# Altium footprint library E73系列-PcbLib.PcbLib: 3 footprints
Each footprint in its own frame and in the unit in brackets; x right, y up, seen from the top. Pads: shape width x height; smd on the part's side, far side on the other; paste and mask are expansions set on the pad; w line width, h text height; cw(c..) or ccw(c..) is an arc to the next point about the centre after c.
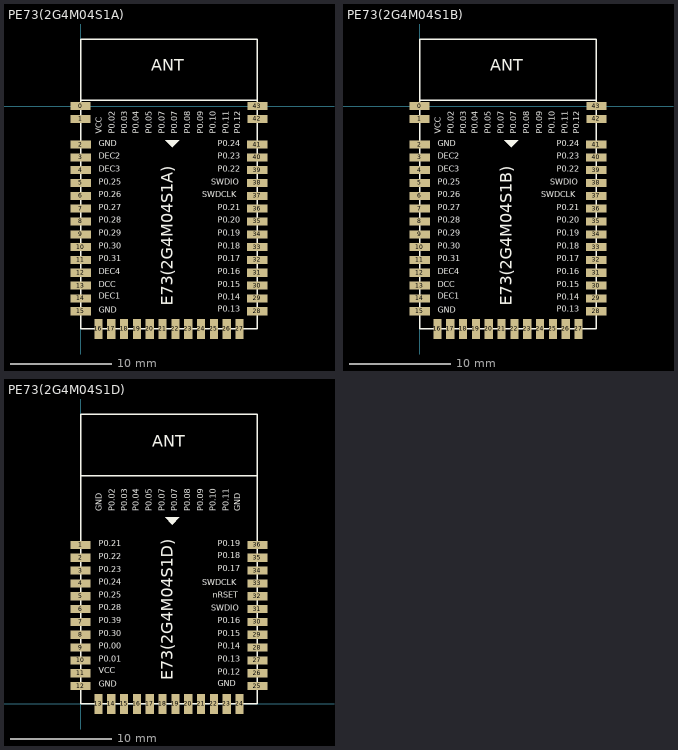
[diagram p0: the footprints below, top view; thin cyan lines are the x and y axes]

## PE73(2G4M04S1A) [mm] "28.7mm*17.5mm*2.60mm-S"
pads (44):
  rect 2x0.8 smd: 0(0,0) 1(0,-1.27) 2(0.02,-3.81) 3(0.02,-5.08) 4(0.02,-6.35) 5(0.02,-7.62) 6(0.02,-8.89) 7(0.02,-10.16) 8(0.02,-11.43) 9(0.02,-12.7) 10(0.02,-13.97) 11(0.02,-15.24) 12(0.02,-16.51) 13(0.02,-17.78) 14(0.02,-19.05) 15(0.02,-20.32) 28(17.48,-20.32) 29(17.48,-19.05) 30(17.48,-17.78) 31(17.48,-16.51) 32(17.48,-15.24) 33(17.48,-13.97) 34(17.48,-12.7) 35(17.48,-11.43) 36(17.48,-10.16) 37(17.48,-8.89) 38(17.48,-7.62) 39(17.48,-6.35) 40(17.48,-5.08) 41(17.48,-3.81) 42(17.5,-1.27) 43(17.5,0)
  rect 0.8x2 smd: 16(1.765,-22.065) 17(3.035,-22.065) 18(4.305,-22.065) 19(5.575,-22.065) 20(6.845,-22.065) 21(8.115,-22.065) 22(9.385,-22.065) 23(10.655,-22.065) 24(11.925,-22.065) 25(13.195,-22.065) 26(14.465,-22.065) 27(15.735,-22.065)
Top Overlay:
  region: 8.37,-3.375 9.76,-3.385 9.08,-4.085 8.36,-3.385
  lines w0.127: 0,0.573 17.467,0.573 ; 0,-22.065 17.5,-22.065 17.5,6.635 0,6.635 0,-22.065
  text "E73(2G4M04S1A)" at 9.525,-19.779 h2
  text "ANT" at 6.985,3.081 h2
  text "GND" at 1.778,-4.158 h1
  text "DEC2" at 1.778,-5.428 h1
  text "DEC3" at 1.778,-6.698 h1
  text "P0.25" at 1.778,-7.968 h1
  text "P0.26" at 1.778,-9.238 h1
  text "P0.27" at 1.778,-10.508 h1
  text "P0.28" at 1.778,-11.778 h1
  text "P0.29" at 1.778,-13.048 h1
  text "P0.30" at 1.778,-14.318 h1
  text "P0.31" at 1.778,-15.588 h1
  text "DEC4" at 1.778,-16.858 h1
  text "DCC" at 1.778,-18.128 h1
  text "DEC1" at 1.778,-19.271 h1
  text "GND" at 1.778,-20.668 h1
  text "P0.13" at 13.589,-20.541 h1
  text "P0.14" at 13.589,-19.398 h1
  text "P0.15" at 13.589,-18.128 h1
  text "P0.16" at 13.589,-16.858 h1
  text "P0.17" at 13.589,-15.588 h1
  text "P0.18" at 13.589,-14.318 h1
  text "P0.19" at 13.589,-13.048 h1
  text "P0.20" at 13.589,-11.778 h1
  text "P0.21" at 13.589,-10.508 h1
  text "SWDCLK" at 12.065,-9.238 h1
  text "SWDIO" at 12.954,-7.968 h1
  text "P0.22" at 13.589,-6.698 h1
  text "P0.23" at 13.589,-5.428 h1
  text "P0.24" at 13.589,-4.158 h1
  text "VCC" at 2.286,-2.761 h1
  text "P0.02" at 3.556,-2.761 h1
  text "P0.03" at 4.826,-2.761 h1
  text "P0.04" at 5.969,-2.761 h1
  text "P0.05" at 7.239,-2.761 h1
  text "P0.07" at 8.509,-2.761 h1
  text "P0.07" at 9.779,-2.761 h1
  text "P0.08" at 11.049,-2.761 h1
  text "P0.09" at 12.319,-2.761 h1
  text "P0.10" at 13.589,-2.761 h1
  text "P0.11" at 14.859,-2.761 h1
  text "P0.12" at 16.009,-2.77 h1

## PE73(2G4M04S1B) [mm] "28.7mm*17.5mm*2.60mm-S"
pads (44):
  rect 2x0.8 smd: 0(0,0) 1(0,-1.27) 2(0.02,-3.81) 3(0.02,-5.08) 4(0.02,-6.35) 5(0.02,-7.62) 6(0.02,-8.89) 7(0.02,-10.16) 8(0.02,-11.43) 9(0.02,-12.7) 10(0.02,-13.97) 11(0.02,-15.24) 12(0.02,-16.51) 13(0.02,-17.78) 14(0.02,-19.05) 15(0.02,-20.32) 28(17.48,-20.32) 29(17.48,-19.05) 30(17.48,-17.78) 31(17.48,-16.51) 32(17.48,-15.24) 33(17.48,-13.97) 34(17.48,-12.7) 35(17.48,-11.43) 36(17.48,-10.16) 37(17.48,-8.89) 38(17.48,-7.62) 39(17.48,-6.35) 40(17.48,-5.08) 41(17.48,-3.81) 42(17.5,-1.27) 43(17.5,0)
  rect 0.8x2 smd: 16(1.765,-22.065) 17(3.035,-22.065) 18(4.305,-22.065) 19(5.575,-22.065) 20(6.845,-22.065) 21(8.115,-22.065) 22(9.385,-22.065) 23(10.655,-22.065) 24(11.925,-22.065) 25(13.195,-22.065) 26(14.465,-22.065) 27(15.735,-22.065)
Top Overlay:
  region: 8.37,-3.375 9.76,-3.385 9.08,-4.085 8.36,-3.385
  lines w0.127: 0,0.573 17.467,0.573 ; 0,-22.065 17.5,-22.065 17.5,6.635 0,6.635 0,-22.065
  text "E73(2G4M04S1B)" at 9.525,-19.779 h2
  text "ANT" at 6.985,3.081 h2
  text "GND" at 1.778,-4.158 h1
  text "DEC2" at 1.778,-5.428 h1
  text "DEC3" at 1.778,-6.698 h1
  text "P0.25" at 1.778,-7.968 h1
  text "P0.26" at 1.778,-9.238 h1
  text "P0.27" at 1.778,-10.508 h1
  text "P0.28" at 1.778,-11.778 h1
  text "P0.29" at 1.778,-13.048 h1
  text "P0.30" at 1.778,-14.318 h1
  text "P0.31" at 1.778,-15.588 h1
  text "DEC4" at 1.778,-16.858 h1
  text "DCC" at 1.778,-18.128 h1
  text "DEC1" at 1.778,-19.271 h1
  text "GND" at 1.778,-20.668 h1
  text "P0.13" at 13.589,-20.541 h1
  text "P0.14" at 13.589,-19.398 h1
  text "P0.15" at 13.589,-18.128 h1
  text "P0.16" at 13.589,-16.858 h1
  text "P0.17" at 13.589,-15.588 h1
  text "P0.18" at 13.589,-14.318 h1
  text "P0.19" at 13.589,-13.048 h1
  text "P0.20" at 13.589,-11.778 h1
  text "P0.21" at 13.589,-10.508 h1
  text "SWDCLK" at 12.065,-9.238 h1
  text "SWDIO" at 12.954,-7.968 h1
  text "P0.22" at 13.589,-6.698 h1
  text "P0.23" at 13.589,-5.428 h1
  text "P0.24" at 13.589,-4.158 h1
  text "VCC" at 2.286,-2.761 h1
  text "P0.02" at 3.556,-2.761 h1
  text "P0.03" at 4.826,-2.761 h1
  text "P0.04" at 5.969,-2.761 h1
  text "P0.05" at 7.239,-2.761 h1
  text "P0.07" at 8.509,-2.761 h1
  text "P0.07" at 9.779,-2.761 h1
  text "P0.08" at 11.049,-2.761 h1
  text "P0.09" at 12.319,-2.761 h1
  text "P0.10" at 13.589,-2.761 h1
  text "P0.11" at 14.859,-2.761 h1
  text "P0.12" at 16.009,-2.77 h1

## PE73(2G4M04S1D) [mm] "28.7mm*17.5mm*2.40mm-S"
pads (36):
  rect 2x0.8 smd: 1(0,15.735) 2(0,14.465) 3(0,13.195) 4(0,11.925) 5(0,10.655) 6(0,9.385) 7(0,8.115) 8(0,6.845) 9(0,5.575) 10(0,4.305) 11(0,3.035) 12(0,1.765) 25(17.5,1.765) 26(17.5,3.035) 27(17.5,4.305) 28(17.5,5.575) 29(17.5,6.845) 30(17.5,8.115) 31(17.5,9.385) 32(17.5,10.655) 33(17.5,11.925) 34(17.5,13.195) 35(17.5,14.465) 36(17.5,15.735)
  rect 0.8x2 smd: 13(1.765,0) 14(3.035,0) 15(4.305,0) 16(5.575,0) 17(6.845,0) 18(8.115,0) 19(9.385,0) 20(10.655,0) 21(11.925,0) 22(13.195,0) 23(14.465,0) 24(15.735,0)
Top Overlay:
  region: 8.37,18.469 9.76,18.459 9.08,17.759 8.36,18.459
  lines w0.127: 0,22.606 17.5,22.606 ; 0,0 17.5,0 17.5,28.7 0,28.7 0,0
  text "ANT" at 7.112,25.052 h2
  text "E73(2G4M04S1D)" at 9.525,2.319 h2
  text "P0.21" at 1.778,15.4 h1
  text "P0.22" at 1.778,14.13 h1
  text "P0.23" at 1.778,12.86 h1
  text "P0.24" at 1.778,11.59 h1
  text "P0.25" at 1.778,10.32 h1
  text "P0.28" at 1.778,9.05 h1
  text "P0.39" at 1.778,7.78 h1
  text "P0.30" at 1.778,6.51 h1
  text "P0.00" at 1.778,5.24 h1
  text "P0.01" at 1.778,3.97 h1
  text "VCC" at 1.778,2.827 h1
  text "GND" at 1.778,1.524 h1
  text "GND" at 13.589,1.557 h1
  text "P0.12" at 13.589,2.7 h1
  text "P0.13" at 13.589,3.97 h1
  text "P0.14" at 13.589,5.24 h1
  text "P0.15" at 13.589,6.51 h1
  text "P0.16" at 13.589,7.78 h1
  text "SWDIO" at 12.954,9.017 h1
  text "nRSET" at 13.081,10.287 h1
  text "P0.17" at 13.589,12.954 h1
  text "SWDCLK" at 12.065,11.557 h1
  text "P0.18" at 13.589,14.224 h1
  text "P0.19" at 13.589,15.4 h1
  text "GND" at 2.286,19.083 h1
  text "P0.02" at 3.556,19.083 h1
  text "P0.03" at 4.826,19.083 h1
  text "P0.04" at 5.969,19.083 h1
  text "P0.05" at 7.239,19.083 h1
  text "P0.07" at 8.509,19.083 h1
  text "P0.07" at 9.779,19.083 h1
  text "P0.08" at 11.049,19.083 h1
  text "P0.09" at 12.319,19.083 h1
  text "P0.10" at 13.589,19.083 h1
  text "P0.11" at 14.859,19.083 h1
  text "GND" at 16.009,19.074 h1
